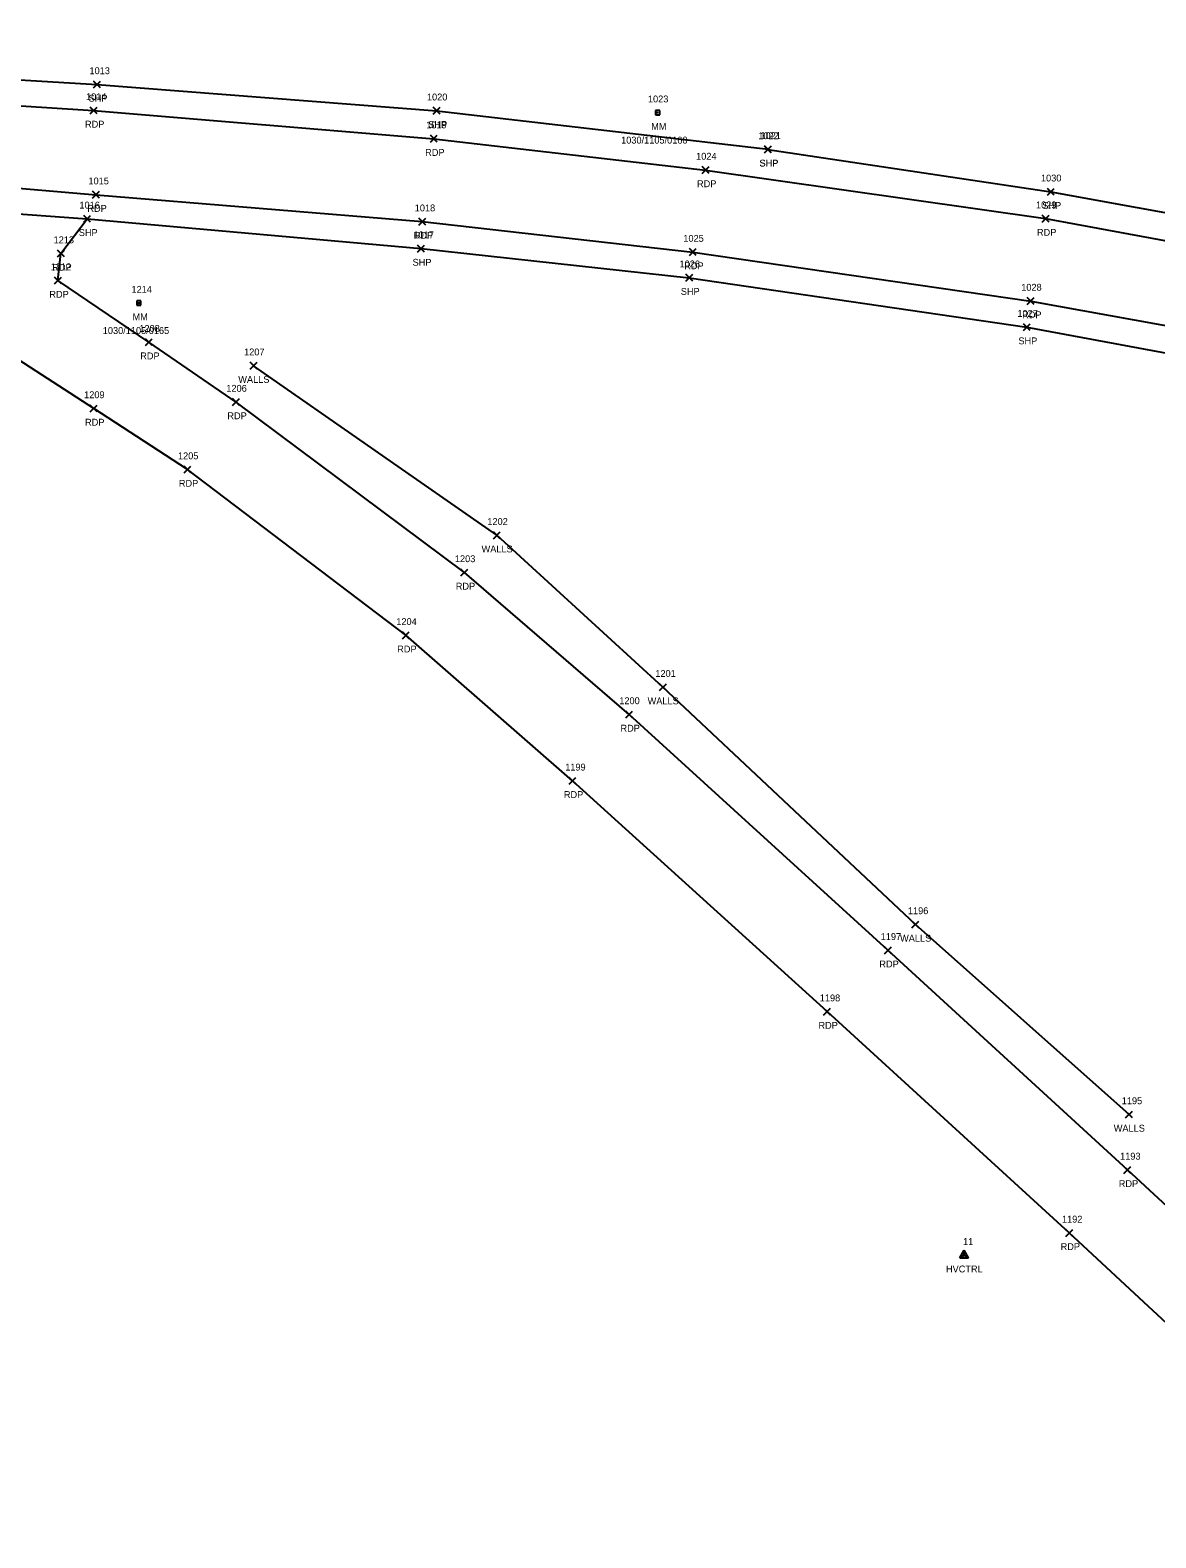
# Model space of a CAD drawing. Extents: x 1519347 to 1522636, y 378779 to 379832.
# Drawn here: x 1520748.2 to 1521076, y 379275.3 to 379714.6 of the extents above; entities that cross this region are included whole.
import ezdxf

# ---------------------------------------------------------------- set-up
doc = ezdxf.new("R2010")
doc.units = 0
for name, color, linetype in [('C_A', 7, 'Continuous'), ('C_I', 7, 'Continuous'), ('CPSM', 7, 'Continuous'), ('L_A', 7, 'Continuous'), ('L_I', 7, 'Continuous'), ('L_TIC', 7, 'Continuous'), ('LWS', 7, 'Continuous'), ('P_A', 7, 'Continuous'), ('P_I', 7, 'Continuous'), ('P_TIC', 7, 'Continuous'), ('PE', 7, 'Continuous'), ('PET', 7, 'Continuous'), ('PSP', 7, 'Continuous'), ('S_A', 7, 'Continuous'), ('S_C', 7, 'Continuous'), ('S_I', 7, 'Continuous'), ('SRM', 7, 'Continuous')]:
    doc.layers.add(name, color=color, linetype=linetype)

msp = doc.modelspace()

# ---------------------------------------------------------------- linework, layer by layer
at = {"layer": 'CPSM'}
for p, q in [((1521018.91, 379356.93), (1521020.16, 379359.1)), ((1521018.91, 379356.93), (1521020.16, 379357.65)), ((1521018.91, 379356.93), (1521021.41, 379356.93)), ((1521021.41, 379356.93), (1521020.16, 379359.1)), ((1521020.16, 379357.65), (1521020.16, 379359.1)), ((1521020.16, 379357.65), (1521020.16, 379357.65)), ((1521020.16, 379357.65), (1521021.41, 379356.93))]:
    msp.add_line(p, q, dxfattribs=at)
at = {"layer": 'L_TIC'}
for points in [[(1520812.25, 379615.82), (1520814.25, 379617.82)], [(1520814.25, 379615.82), (1520812.25, 379617.82)], [(1520883.09, 379566.42), (1520885.09, 379568.42)], [(1520885.09, 379566.42), (1520883.09, 379568.42)], [(1520931.43, 379522.15), (1520933.43, 379524.15)], [(1520933.43, 379522.15), (1520931.43, 379524.15)], [(1521004.95, 379453.02), (1521006.95, 379455.02)], [(1521006.95, 379453.02), (1521004.95, 379455.02)], [(1521067.16, 379397.66), (1521069.16, 379399.66)], [(1521069.16, 379397.66), (1521067.16, 379399.66)]]:
    msp.add_lwpolyline(points, dxfattribs=at)
at = {"layer": 'LWS'}
msp.add_lwpolyline([(1521068.16, 379398.66), (1521005.95, 379454.02), (1520932.43, 379523.15), (1520884.09, 379567.42), (1520813.25, 379616.82)], dxfattribs=at)
at = {"layer": 'P_TIC'}
for points in [[(1520766.67, 379697.75), (1520768.67, 379699.75)], [(1520768.67, 379697.75), (1520766.67, 379699.75)], [(1520765.67, 379690.18), (1520767.67, 379692.18)], [(1520767.67, 379690.18), (1520765.67, 379692.18)], [(1520865.58, 379690.1), (1520867.58, 379692.1)], [(1520867.58, 379690.1), (1520865.58, 379692.1)], [(1520864.72, 379681.95), (1520866.72, 379683.95)], [(1520866.72, 379681.95), (1520864.72, 379683.95)], [(1520961.98, 379678.81), (1520963.98, 379680.81)], [(1520963.98, 379678.81), (1520961.98, 379680.81)], [(1520962.04, 379678.86), (1520964.04, 379680.86)], [(1520964.04, 379678.86), (1520962.04, 379680.86)], [(1520943.87, 379672.83), (1520945.87, 379674.83)], [(1520945.87, 379672.83), (1520943.87, 379674.83)], [(1520766.36, 379665.64), (1520768.36, 379667.64)], [(1520768.36, 379665.64), (1520766.36, 379667.64)], [(1521044.38, 379666.49), (1521046.38, 379668.49)], [(1521046.38, 379666.49), (1521044.38, 379668.49)], [(1520763.8, 379658.6), (1520765.8, 379660.6)], [(1520765.8, 379658.6), (1520763.8, 379660.6)], [(1520861.37, 379657.78), (1520863.37, 379659.78)], [(1520863.37, 379657.78), (1520861.37, 379659.78)], [(1521042.86, 379658.67), (1521044.86, 379660.67)], [(1521044.86, 379658.67), (1521042.86, 379660.67)], [(1520756.14, 379648.49), (1520758.14, 379650.49)], [(1520758.14, 379648.49), (1520756.14, 379650.49)], [(1520861, 379649.94), (1520863, 379651.94)], [(1520863, 379649.94), (1520861, 379651.94)], [(1520940.16, 379648.92), (1520942.16, 379650.92)], [(1520942.16, 379648.92), (1520940.16, 379650.92)], [(1520755.28, 379640.62), (1520757.28, 379642.62)], [(1520757.28, 379640.62), (1520755.28, 379642.62)], [(1520939.1, 379641.46), (1520941.1, 379643.46)], [(1520941.1, 379641.46), (1520939.1, 379643.46)], [(1521038.54, 379634.66), (1521040.54, 379636.66)], [(1521040.54, 379634.66), (1521038.54, 379636.66)], [(1521037.42, 379627.05), (1521039.42, 379629.05)], [(1521039.42, 379627.05), (1521037.42, 379629.05)], [(1520781.76, 379622.68), (1520783.76, 379624.68)], [(1520783.76, 379622.68), (1520781.76, 379624.68)], [(1520807.13, 379605.22), (1520809.13, 379607.22)], [(1520809.13, 379605.22), (1520807.13, 379607.22)], [(1520765.68, 379603.35), (1520767.68, 379605.35)], [(1520767.68, 379603.35), (1520765.68, 379605.35)], [(1520793, 379585.56), (1520795, 379587.56)], [(1520795, 379585.56), (1520793, 379587.56)], [(1520873.63, 379555.58), (1520875.63, 379557.58)], [(1520875.63, 379555.58), (1520873.63, 379557.58)], [(1520856.57, 379537.26), (1520858.57, 379539.26)], [(1520858.57, 379537.26), (1520856.57, 379539.26)], [(1520921.59, 379514.2), (1520923.59, 379516.2)], [(1520923.59, 379514.2), (1520921.59, 379516.2)], [(1520905.12, 379494.86), (1520907.12, 379496.86)], [(1520907.12, 379494.86), (1520905.12, 379496.86)], [(1520996.97, 379445.49), (1520998.97, 379447.49)], [(1520998.97, 379445.49), (1520996.97, 379447.49)], [(1520979.24, 379427.62), (1520981.24, 379429.62)], [(1520981.24, 379427.62), (1520979.24, 379429.62)], [(1521066.69, 379381.51), (1521068.69, 379383.51)], [(1521068.69, 379381.51), (1521066.69, 379383.51)], [(1521049.75, 379363.16), (1521051.75, 379365.16)], [(1521051.75, 379363.16), (1521049.75, 379365.16)]]:
    msp.add_lwpolyline(points, dxfattribs=at)
at = {"layer": 'PE'}
for points in [[(1520500.29, 379707.13), (1520597.92, 379701.55), (1520704.39, 379695.17), (1520766.67, 379691.18), (1520865.72, 379682.95), (1520944.87, 379673.83), (1521043.86, 379659.67), (1521144.22, 379641.18), (1521240.97, 379619.56), (1521339.55, 379594.81), (1521436.37, 379566.43), (1521529.39, 379535.32), (1521632.62, 379496.8)], [(1520499.12, 379683.2), (1520597.12, 379677.59), (1520702.85, 379672.1), (1520767.36, 379666.64), (1520862.37, 379658.78), (1520941.16, 379649.92), (1521039.54, 379635.66), (1521138.91, 379617.62), (1521235.57, 379596.13), (1521333.44, 379571.25), (1521428.97, 379543.22), (1521521.96, 379512.45), (1521622.97, 379474.43)]]:
    msp.add_lwpolyline(points, dxfattribs=at)
at = {"layer": 'PET'}
for points in [[(1520757.14, 379649.49), (1520764.8, 379659.6)], [(1521585.34, 378845.78), (1521563.15, 378884.68), (1521538.32, 378926.95), (1521509.26, 378967.74), (1521474.33, 379006.93), (1521436.59, 379043.66), (1521409.99, 379067.83), (1521358.14, 379115.1), (1521306.99, 379161.95), (1521255.2, 379209.61), (1521217.12, 379244.56), (1521164.23, 379293.24), (1521067.69, 379382.51), (1520997.97, 379446.49), (1520922.59, 379515.2), (1520874.63, 379556.58), (1520808.13, 379606.22), (1520782.76, 379623.68), (1520756.28, 379641.62), (1520757.14, 379649.49)], [(1521566.64, 378831.03), (1521543.56, 378872.83), (1521519.09, 378912.94), (1521489.55, 378952.75), (1521455.86, 378990.48), (1521419.87, 379025.89), (1521341.37, 379097.91), (1521290.76, 379143.7), (1521238.48, 379191.54), (1521199.1, 379228.33), (1521145.7, 379275.98), (1521050.75, 379364.16), (1520980.24, 379428.62), (1520906.12, 379495.86), (1520857.57, 379538.26), (1520794, 379586.56), (1520766.68, 379604.35), (1520729.49, 379628.42), (1520699.13, 379644.75)]]:
    msp.add_lwpolyline(points, dxfattribs=at)
at = {"layer": 'PSP'}
for points in [[(1520500.66, 379714.58), (1520598.16, 379708.86), (1520704.83, 379702.57), (1520767.67, 379698.75), (1520866.58, 379691.1), (1520963.04, 379679.86), (1520962.98, 379679.81), (1521045.38, 379667.49), (1521145.9, 379649.23), (1521242.81, 379627.02), (1521341.58, 379601.87), (1521438.52, 379574.01), (1521531.82, 379542.79), (1521635.1, 379503.97)], [(1520498.56, 379673.83), (1520597.58, 379669.39), (1520622.82, 379668.23), (1520701.9, 379664.18), (1520764.8, 379659.6), (1520862, 379650.94), (1520940.1, 379642.46), (1521038.42, 379628.05), (1521137.18, 379609.65), (1521233.6, 379588.29), (1521331.39, 379563.44), (1521426.62, 379535.62), (1521519.02, 379505.15), (1521619.86, 379467.25)]]:
    msp.add_lwpolyline(points, dxfattribs=at)
at = {"layer": 'SRM'}
for p, q in [((1520931.49, 379691.19), (1520930.24, 379691.19)), ((1520930.24, 379691.19), (1520930.24, 379689.94)), ((1520931.49, 379691.19), (1520930.24, 379691.19)), ((1520930.24, 379691.19), (1520930.24, 379689.94)), ((1520930.24, 379689.94), (1520931.49, 379689.94)), ((1520930.24, 379689.94), (1520931.49, 379689.94)), ((1520931.49, 379689.94), (1520931.49, 379691.19)), ((1520931.49, 379689.94), (1520931.49, 379691.19)), ((1520780.46, 379635.72), (1520779.21, 379635.72)), ((1520779.21, 379635.72), (1520779.21, 379634.47)), ((1520780.46, 379635.72), (1520779.21, 379635.72)), ((1520779.21, 379635.72), (1520779.21, 379634.47)), ((1520779.21, 379634.47), (1520780.46, 379634.47)), ((1520779.21, 379634.47), (1520780.46, 379634.47)), ((1520780.46, 379634.47), (1520780.46, 379635.72)), ((1520780.46, 379634.47), (1520780.46, 379635.72))]:
    msp.add_line(p, q, dxfattribs=at)
for centre in [(1520930.84, 379690.53), (1520779.82, 379635.06)]:
    msp.add_circle(centre, 0.0833, dxfattribs=at)

# ---------------------------------------------------------------- texts
at = {"layer": 'C_A'}
msp.add_text('HVCTRL', height=2, dxfattribs=at).set_placement((1521014.85, 379352.65))
at = {"layer": 'C_I'}
msp.add_text('11', height=2, dxfattribs=at).set_placement((1521019.83, 379360.65))
at = {"layer": 'L_A'}
for p in [(1520808.79, 379611.82), (1520879.63, 379562.42), (1520927.98, 379518.15), (1521001.49, 379449.02), (1521063.71, 379393.66)]:
    msp.add_text('WALLS', height=2, dxfattribs=at).set_placement(p)
at = {"layer": 'L_I'}
for s, p in [('1207', (1520810.48, 379619.82)), ('1202', (1520881.32, 379570.42)), ('1201', (1520930.23, 379526.15)), ('1196', (1521003.77, 379457.02)), ('1195', (1521066.04, 379401.66))]:
    msp.add_text(s, height=2, dxfattribs=at).set_placement(p)
at = {"layer": 'P_A'}
for s, p in [('SHP', (1520765.2, 379693.75)), ('RDP', (1520764.16, 379686.18)), ('SHP', (1520864.11, 379686.1)), ('RDP', (1520863.21, 379677.95)), ('SHP', (1520960.52, 379674.81)), ('SHP', (1520960.57, 379674.86)), ('RDP', (1520942.36, 379668.83)), ('RDP', (1520764.85, 379661.64)), ('SHP', (1521042.91, 379662.49)), ('SHP', (1520762.34, 379654.6)), ('RDP', (1520859.86, 379653.78)), ('RDP', (1521041.35, 379654.67)), ('RDP', (1520754.63, 379644.49)), ('SHP', (1520859.54, 379645.94)), ('RDP', (1520938.64, 379644.92)), ('RDP', (1520753.77, 379636.62)), ('SHP', (1520937.64, 379637.46)), ('RDP', (1521037.03, 379630.66)), ('SHP', (1521035.95, 379623.05)), ('RDP', (1520780.24, 379618.68)), ('RDP', (1520764.17, 379599.35)), ('RDP', (1520805.62, 379601.22)), ('RDP', (1520791.49, 379581.56)), ('RDP', (1520872.12, 379551.58)), ('RDP', (1520855.06, 379533.26)), ('RDP', (1520920.07, 379510.2)), ('RDP', (1520903.6, 379490.86)), ('RDP', (1520995.46, 379441.49)), ('RDP', (1520977.72, 379423.62)), ('RDP', (1521065.17, 379377.51)), ('RDP', (1521048.24, 379359.16))]:
    msp.add_text(s, height=2, dxfattribs=at).set_placement(p)
at = {"layer": 'P_I'}
for s, p in [('1013', (1520765.46, 379701.75)), ('1014', (1520764.46, 379694.18)), ('1020', (1520863.72, 379694.1)), ('1019', (1520863.51, 379685.95)), ('1022', (1520960.21, 379682.81)), ('1021', (1520960.83, 379682.86)), ('1024', (1520942.1, 379676.83)), ('1015', (1520765.16, 379669.64)), ('1030', (1521042.52, 379670.49)), ('1016', (1520762.54, 379662.6)), ('1018', (1520860.17, 379661.78)), ('1029', (1521041.08, 379662.67)), ('1213', (1520755.01, 379652.49)), ('1017', (1520859.8, 379653.94)), ('1025', (1520938.38, 379652.92)), ('1212', (1520754.16, 379644.62)), ('1026', (1520937.27, 379645.46)), ('1028', (1521036.77, 379638.66)), ('1027', (1521035.65, 379631.05)), ('1208', (1520779.98, 379626.68)), ('1206', (1520805.31, 379609.22)), ('1209', (1520763.9, 379607.35)), ('1205', (1520791.23, 379589.56)), ('1203', (1520871.86, 379559.58)), ('1204', (1520854.8, 379541.26)), ('1200', (1520919.73, 379518.2)), ('1199', (1520903.98, 379498.86)), ('1197', (1520995.85, 379449.49)), ('1198', (1520978.11, 379431.62)), ('1193', (1521065.56, 379385.51)), ('1192', (1521048.63, 379367.16))]:
    msp.add_text(s, height=2, dxfattribs=at).set_placement(p)
at = {"layer": 'S_A'}
for p in [(1520929.03, 379685.53), (1520778, 379630.06)]:
    msp.add_text('MM', height=2, dxfattribs=at).set_placement(p)
at = {"layer": 'S_C'}
for s, p in [('1030/1105/0160', (1520920.27, 379681.53)), ('1030/1105/0165', (1520769.33, 379626.06))]:
    msp.add_text(s, height=2, dxfattribs=at).set_placement(p)
at = {"layer": 'S_I'}
for s, p in [('1023', (1520928.07, 379693.53)), ('1214', (1520777.69, 379638.06))]:
    msp.add_text(s, height=2, dxfattribs=at).set_placement(p)

doc.saveas('drawing.dxf')
